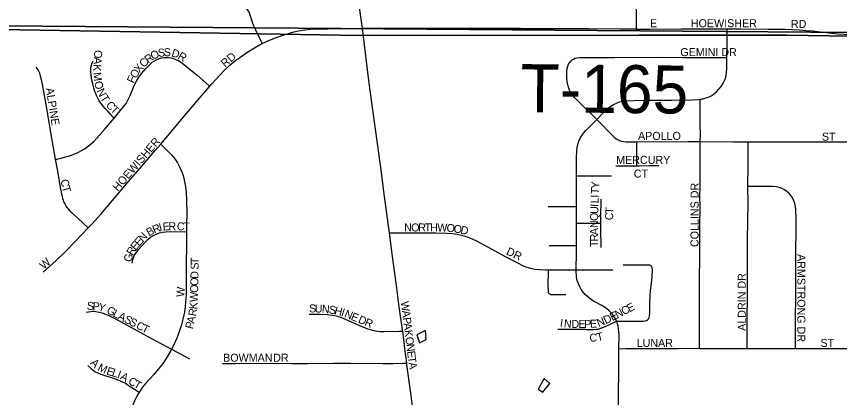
# Model space of a CAD drawing. Extents: x 0 to 1391, y -24 to 440.
# Drawn here: x 523.79 to 543.27, y 306.2 to 315.22 of the extents above; entities that cross this region are included whole.
import ezdxf

# ---------------------------------------------------------------- set-up
doc = ezdxf.new("R2010")
doc.units = 0
for name, color, linetype in [('GM_X_City_Street', 7, 'Continuous'), ('GM_X_City_Street_Text', 7, 'Continuous'), ('GM_X_Corporation', 7, 'Continuous'), ('GM_X_County_Road', 7, 'Continuous'), ('GM_X_Minor_Lake', 7, 'Continuous'), ('GM_X_Section', 7, 'Continuous'), ('GM_X_Township', 7, 'Continuous'), ('GM_X_Township_Road', 7, 'Continuous'), ('GM_X_Township_Road_Text', 7, 'Continuous')]:
    doc.layers.add(name, color=color, linetype=linetype)

msp = doc.modelspace()

# ---------------------------------------------------------------- linework, layer by layer
at = {"layer": 'GM_X_City_Street'}
for points in [[(529.045, 315.613), (529.052, 315.609), (529.108, 315.56), (529.165, 315.505), (529.199, 315.464), (529.232, 315.42), (529.255, 315.388), (529.279, 315.35), (529.299, 315.313), (529.312, 315.277), (529.327, 315.232), (529.362, 315.114), (529.38, 315.062), (529.398, 315.022), (529.424, 314.959), (529.448, 314.908), (529.596, 314.613), (529.611, 314.582)], [(529.611, 314.582), (529.779, 314.661), (529.965, 314.733), (530.154, 314.796), (530.358, 314.854), (530.468, 314.88), (530.615, 314.906), (530.752, 314.923), (530.926, 314.932), (531.163, 314.932), (531.986, 314.935)], [(532.618, 310.102), (532.588, 310.318), (532.505, 310.958), (532.413, 311.648), (532.256, 312.781), (532.14, 313.643), (531.986, 314.935)], [(538.458, 314.922), (538.771, 314.921), (539.529, 314.926), (539.927, 314.929), (540.474, 314.929), (540.607, 314.929)], [(540.605, 314.252), (540.608, 314.566), (540.608, 314.814), (540.607, 314.929)], [(540.607, 314.929), (540.934, 314.929), (541.58, 314.924), (541.99, 314.917), (542.322, 314.902), (542.47, 314.89), (542.63, 314.877), (542.808, 314.859), (543.23, 314.813), (543.377, 314.799), (543.51, 314.787)], [(528.37, 313.568), (528.42, 313.627), (528.611, 313.84), (528.715, 313.948), (528.844, 314.066), (528.989, 314.186), (529.078, 314.253), (529.243, 314.366), (529.423, 314.478), (529.575, 314.565), (529.611, 314.582)], [(526.104, 312.814), (526.075, 312.847), (525.964, 312.969), (525.903, 313.036), (525.846, 313.1), (525.822, 313.131), (525.793, 313.169), (525.771, 313.203), (525.747, 313.243), (525.716, 313.301), (525.691, 313.354), (525.671, 313.399), (525.653, 313.446), (525.634, 313.5), (525.619, 313.553), (525.601, 313.628), (525.582, 313.711), (525.561, 313.833), (525.553, 313.92), (525.552, 313.944), (525.554, 313.982), (525.557, 314.008), (525.563, 314.043), (525.57, 314.071), (525.58, 314.103), (525.594, 314.137), (525.61, 314.172)], [(526.104, 312.814), (526.321, 313.071), (526.387, 313.161), (526.425, 313.225), (526.479, 313.337), (526.541, 313.488), (526.575, 313.569), (526.608, 313.64), (526.635, 313.69), (526.693, 313.785), (526.759, 313.875), (526.856, 313.989), (526.943, 314.078), (527.008, 314.136), (527.057, 314.172), (527.116, 314.202), (527.176, 314.227), (527.227, 314.24), (527.278, 314.249), (527.331, 314.253), (527.393, 314.252), (527.454, 314.243), (527.514, 314.227), (527.583, 314.198), (527.627, 314.177), (527.662, 314.156), (527.702, 314.13), (527.742, 314.1), (527.829, 314.03), (528.067, 313.83), (528.346, 313.589), (528.37, 313.568)], [(537.525, 312.783), (537.187, 313.116), (537.01, 313.292), (536.952, 313.358), (536.922, 313.4), (536.89, 313.456), (536.861, 313.527), (536.839, 313.6), (536.826, 313.675), (536.819, 313.789), (536.819, 313.915), (536.826, 313.991), (536.837, 314.042), (536.856, 314.091), (536.877, 314.125), (536.911, 314.166), (536.941, 314.192), (536.975, 314.214), (537.011, 314.23), (537.05, 314.24), (537.114, 314.248), (537.227, 314.251), (537.624, 314.248), (537.947, 314.249), (538.966, 314.254), (539.55, 314.249), (540.356, 314.249), (540.48, 314.25), (540.605, 314.252)], [(539.972, 313.262), (540.012, 313.267), (540.082, 313.284), (540.139, 313.299), (540.182, 313.315), (540.229, 313.34), (540.271, 313.368), (540.319, 313.402), (540.361, 313.439), (540.414, 313.498), (540.468, 313.563), (540.508, 313.624), (540.542, 313.688), (540.568, 313.755), (540.587, 313.825), (540.598, 313.897), (540.603, 313.982), (540.605, 314.193), (540.605, 314.252)], [(524.719, 311.84), (524.671, 312.112), (524.618, 312.43), (524.529, 312.957), (524.443, 313.447), (524.395, 313.69), (524.366, 313.811), (524.357, 313.843), (524.345, 313.879), (524.337, 313.896), (524.322, 313.928), (524.306, 313.955), (524.285, 313.989), (524.262, 314.021)], [(527.207, 312.202), (527.492, 312.54), (527.733, 312.825), (528.041, 313.182), (528.37, 313.568)], [(537.525, 312.783), (537.687, 312.948), (537.798, 313.05), (537.824, 313.072), (537.858, 313.096), (537.922, 313.137), (537.991, 313.171), (538.063, 313.197), (538.137, 313.215), (538.213, 313.225), (538.4, 313.233), (538.699, 313.239), (539.295, 313.243), (539.779, 313.249), (539.927, 313.257), (539.972, 313.262)], [(539.975, 312.261), (539.977, 312.428), (539.975, 312.652), (539.973, 313.112), (539.972, 313.262)], [(524.719, 311.84), (524.747, 311.846), (524.88, 311.878), (524.934, 311.889), (524.988, 311.903), (525.047, 311.922), (525.094, 311.939), (525.243, 312.001), (525.332, 312.046), (525.417, 312.098), (525.47, 312.133), (525.527, 312.179), (525.622, 312.261), (525.7, 312.341), (525.879, 312.548), (526.104, 312.814)], [(537.049, 311.45), (537.049, 311.632), (537.048, 311.894), (537.054, 312.032), (537.065, 312.12), (537.081, 312.194), (537.104, 312.267), (537.134, 312.337), (537.172, 312.404), (537.217, 312.465), (537.267, 312.522), (537.525, 312.783)], [(537.525, 312.783), (537.596, 312.711), (537.847, 312.453), (537.937, 312.365), (537.988, 312.326), (538.044, 312.293), (538.105, 312.27), (538.156, 312.258), (538.219, 312.252), (538.471, 312.253)], [(525.495, 310.218), (525.587, 310.314), (525.794, 310.545), (526.109, 310.912), (526.435, 311.304), (526.719, 311.633), (527.067, 312.038), (527.207, 312.202)], [(527.207, 312.202), (527.227, 312.182), (527.387, 312.024), (527.463, 311.944), (527.54, 311.848), (527.602, 311.757), (527.655, 311.66), (527.7, 311.56), (527.736, 311.456), (527.773, 311.313), (527.794, 311.192), (527.808, 311.058), (527.815, 310.872), (527.824, 310.55), (527.821, 310.289), (527.819, 310.12)], [(538.471, 312.253), (539.684, 312.261), (539.975, 312.261)], [(538.477, 311.688), (538.476, 311.736), (538.474, 311.846), (538.471, 312.042), (538.471, 312.153), (538.471, 312.253)], [(539.959, 307.364), (539.959, 307.46), (539.957, 307.843), (539.959, 308.054), (539.958, 308.179), (539.958, 308.452), (539.958, 309.048), (539.964, 309.458), (539.966, 309.645), (539.963, 309.968), (539.962, 310.29), (539.968, 310.688), (539.967, 310.999), (539.969, 311.16), (539.975, 311.608), (539.972, 311.981), (539.975, 312.261)], [(539.975, 312.261), (540.751, 312.256), (541.105, 312.254)], [(541.1, 311.196), (541.107, 311.713), (541.106, 312.098), (541.105, 312.254)], [(541.105, 312.254), (541.372, 312.253), (542.688, 312.25), (542.949, 312.251), (543.357, 312.251), (543.495, 312.251)], [(525.495, 310.218), (525.486, 310.226), (525.244, 310.445), (525.091, 310.591), (525.047, 310.639), (525.016, 310.674), (524.994, 310.703), (524.972, 310.734), (524.954, 310.765), (524.936, 310.799), (524.919, 310.834), (524.907, 310.867), (524.895, 310.906), (524.882, 310.951), (524.843, 311.133), (524.762, 311.598), (524.719, 311.84)], [(537.975, 311.687), (538.477, 311.688)], [(538.477, 311.688), (538.54, 311.688), (538.774, 311.693), (538.992, 311.696)], [(537.047, 310.721), (537.049, 311.26), (537.049, 311.45)], [(537.049, 311.45), (537.191, 311.449), (537.381, 311.449), (537.756, 311.448), (537.872, 311.45)], [(541.086, 307.361), (541.086, 307.552), (541.085, 308.086), (541.089, 308.583), (541.091, 308.931), (541.094, 309.278), (541.093, 309.639), (541.095, 309.962), (541.097, 310.334), (541.104, 310.831), (541.1, 311.154), (541.1, 311.196)], [(542.229, 307.36), (542.229, 307.488), (542.23, 308.097), (542.232, 308.569), (542.238, 309.687), (542.24, 310.134), (542.24, 310.457), (542.239, 310.643), (542.231, 310.717), (542.215, 310.79), (542.191, 310.86), (542.158, 310.927), (542.123, 310.979), (542.082, 311.025), (542.026, 311.074), (541.965, 311.117), (541.91, 311.145), (541.84, 311.171), (541.767, 311.187), (541.693, 311.195), (541.457, 311.197), (541.283, 311.199), (541.246, 311.199), (541.1, 311.196)], [(537.625, 310.325), (537.625, 310.464), (537.628, 310.9)], [(536.379, 310.724), (536.578, 310.723), (536.908, 310.722), (537.047, 310.721)], [(537.045, 310.33), (537.046, 310.428), (537.047, 310.721)], [(537.042, 309.799), (537.045, 310.33)], [(537.045, 310.33), (537.175, 310.328), (537.321, 310.326), (537.446, 310.326), (537.571, 310.326), (537.625, 310.325)], [(537.626, 309.753), (537.625, 310.187), (537.625, 310.325)], [(524.43, 309.166), (524.736, 309.446), (524.941, 309.643), (525.2, 309.911), (525.495, 310.218)], [(526.532, 309.384), (526.548, 309.47), (526.563, 309.517), (526.583, 309.562), (526.616, 309.615), (526.686, 309.702), (526.832, 309.87), (526.902, 309.94), (526.97, 309.994), (527.022, 310.027), (527.1, 310.066), (527.181, 310.097), (527.253, 310.115), (527.326, 310.126), (527.438, 310.13), (527.796, 310.121), (527.819, 310.12)], [(527.819, 310.12), (527.816, 309.855), (527.813, 309.308), (527.814, 308.873), (527.808, 308.638), (527.785, 308.354), (527.767, 308.22), (527.74, 308.087), (527.689, 307.896), (527.637, 307.731), (527.589, 307.605), (527.518, 307.447), (527.465, 307.343)], [(532.618, 310.102), (532.813, 310.1), (533.379, 310.096), (533.715, 310.096), (533.975, 310.095), (534.11, 310.086), (534.22, 310.071), (534.328, 310.047), (534.434, 310.016), (534.537, 309.977), (534.66, 309.92), (534.956, 309.763), (535.359, 309.541), (535.667, 309.378), (535.78, 309.322), (535.874, 309.285), (535.959, 309.26), (536.058, 309.24), (536.159, 309.229), (536.309, 309.223), (536.38, 309.223)], [(532.933, 307.773), (532.929, 307.805), (532.852, 308.347), (532.785, 308.851), (532.695, 309.542), (532.618, 310.102)], [(536.402, 309.798), (536.577, 309.798), (536.761, 309.799), (536.934, 309.799), (537.042, 309.799)], [(537.04, 309.224), (537.042, 309.645), (537.042, 309.799)], [(537.992, 308.011), (538.257, 308.011), (538.41, 308.009), (538.62, 308.01), (538.666, 308.016), (538.698, 308.026), (538.727, 308.042), (538.749, 308.064), (538.763, 308.092), (538.772, 308.125), (538.777, 308.196), (538.784, 308.444), (538.786, 308.607), (538.796, 308.732), (538.819, 308.905), (538.836, 309.064), (538.843, 309.235), (538.838, 309.269), (538.827, 309.299), (538.815, 309.314), (538.8, 309.325), (538.781, 309.332), (538.736, 309.335), (538.4, 309.334), (538.151, 309.337)], [(536.795, 308.632), (536.467, 308.629), (536.436, 308.635), (536.417, 308.645), (536.394, 308.665), (536.384, 308.68), (536.38, 308.7), (536.379, 308.909), (536.38, 309.127), (536.38, 309.223)], [(536.38, 309.223), (536.63, 309.223), (536.88, 309.224), (537.04, 309.224)], [(537.992, 308.011), (537.975, 308.045), (537.95, 308.09), (537.922, 308.133), (537.886, 308.179), (537.85, 308.221), (537.812, 308.26), (537.762, 308.301), (537.708, 308.34), (537.644, 308.38), (537.462, 308.478), (537.378, 308.533), (537.318, 308.58), (537.262, 308.632), (537.211, 308.689), (537.16, 308.762), (537.118, 308.84), (537.092, 308.894), (537.074, 308.935), (537.061, 308.973), (537.052, 309.011), (537.047, 309.06), (537.04, 309.197), (537.04, 309.224)], [(537.04, 309.224), (537.459, 309.22), (537.802, 309.22), (537.902, 309.22)], [(525.444, 308.225), (525.502, 308.233), (525.556, 308.24), (525.595, 308.242), (525.637, 308.242), (525.676, 308.237), (525.715, 308.232), (525.752, 308.225), (525.821, 308.206), (525.88, 308.184), (525.966, 308.148), (526.136, 308.062), (526.345, 307.951), (526.868, 307.665), (527.108, 307.535), (527.465, 307.343)], [(530.722, 308.176), (530.965, 308.178), (531.151, 308.166), (531.274, 308.151), (531.359, 308.133), (531.416, 308.117), (531.466, 308.101), (531.57, 308.059), (531.966, 307.88), (532.027, 307.855), (532.082, 307.836), (532.189, 307.804), (532.245, 307.789), (532.298, 307.78), (532.396, 307.767), (532.496, 307.763), (532.854, 307.771), (532.933, 307.773)], [(536.606, 307.823), (536.803, 307.821), (537.125, 307.819), (537.262, 307.816), (537.29, 307.815), (537.328, 307.814), (537.354, 307.814), (537.363, 307.814), (537.393, 307.814), (537.449, 307.814), (537.509, 307.816), (537.558, 307.823), (537.618, 307.84), (537.767, 307.901), (537.858, 307.946), (537.992, 308.011)], [(538.051, 307.357), (538.053, 307.689), (538.05, 307.768), (538.043, 307.831), (538.032, 307.891), (538.018, 307.941), (537.998, 307.997), (537.992, 308.011)], [(533.029, 307.017), (532.986, 307.361), (532.933, 307.773)], [(527.465, 307.343), (527.451, 307.315), (527.364, 307.166), (527.283, 307.042), (527.194, 306.924), (527.043, 306.744), (526.859, 306.542), (526.78, 306.444), (526.709, 306.34), (526.701, 306.326)], [(527.465, 307.343), (527.475, 307.337), (527.8, 307.167), (527.889, 307.121)], [(538.092, 304.699), (538.09, 304.733), (538.068, 305.03), (538.054, 305.354), (538.049, 305.664), (538.043, 306.124), (538.048, 306.982), (538.051, 307.357)], [(538.051, 307.357), (538.208, 307.36), (538.458, 307.364), (539.055, 307.361), (539.452, 307.362), (539.725, 307.366), (539.959, 307.364)], [(539.959, 307.364), (540.397, 307.36), (541.086, 307.361)], [(541.086, 307.361), (541.366, 307.362), (542.061, 307.359), (542.229, 307.36)], [(542.229, 307.36), (542.534, 307.36), (543.242, 307.362), (543.329, 307.361), (543.483, 307.36)], [(525.482, 306.956), (525.568, 306.88), (525.627, 306.835), (525.664, 306.812), (525.703, 306.792), (525.752, 306.771), (525.794, 306.753), (526.127, 306.646), (526.232, 306.607), (526.322, 306.564), (526.372, 306.538), (526.441, 306.496), (526.671, 306.346), (526.701, 306.326)], [(528.667, 307.005), (528.976, 307.007), (529.348, 307.012), (529.622, 307.009), (529.883, 307.011), (530.305, 307.01), (530.678, 307.009), (531.287, 307.013), (531.71, 307.013), (532.455, 307.01), (532.716, 307.009), (532.929, 307.014), (533.029, 307.017)], [(533.208, 305.671), (533.179, 305.883), (533.119, 306.363), (533.033, 306.979), (533.029, 307.017)], [(526.701, 306.326), (526.645, 306.232), (526.589, 306.12), (526.541, 306.004), (526.511, 305.915)]]:
    msp.add_lwpolyline(points, dxfattribs=at)
at = {"layer": 'GM_X_Corporation'}
msp.add_lwpolyline([(543.512, 319.472), (541.992, 319.486), (542.007, 316.193), (538.456, 316.162), (538.458, 314.922), (535.727, 314.933), (531.986, 314.935), (531.717, 316.828), (528.397, 316.553), (528.413, 317.001), (529.778, 317.193), (530.212, 317.944), (531.533, 318.118), (531.399, 319.019), (532.093, 319.148), (531.917, 320.165), (531.256, 320.053), (531.2, 320.498), (530.847, 320.443), (530.739, 321.001), (530.415, 321.61), (529.673, 321.397), (527.382, 319.542), (523.111, 315.958)], dxfattribs=at)
at = {"layer": 'GM_X_County_Road'}
msp.add_lwpolyline([(531.986, 314.935), (531.89, 315.606), (531.819, 316.096), (531.756, 316.551), (531.717, 316.828)], dxfattribs=at)
at = {"layer": 'GM_X_Minor_Lake'}
for p, q in [((533.49, 307.572), (533.471, 307.786)), ((533.271, 307.684), (533.328, 307.497)), ((533.328, 307.497), (533.49, 307.572)), ((536.253, 306.328), (536.413, 306.532)), ((536.413, 306.532), (536.279, 306.65)), ((536.142, 306.397), (536.253, 306.328))]:
    msp.add_line(p, q, dxfattribs=at)
for points in [[(533.471, 307.786), (533.271, 307.684)], [(536.279, 306.65), (536.142, 306.397)]]:
    msp.add_lwpolyline(points, dxfattribs=at)
at = {"layer": 'GM_X_Section'}
for points in [[(543.597, 335.27), (543.606, 334.944), (543.593, 314.84), (523.385, 314.999), (523.728, 335.34)], [(543.593, 314.84), (543.458, 295.101), (523.431, 295.166), (523.385, 314.999)]]:
    msp.add_lwpolyline(points, close=True, dxfattribs=at)
at = {"layer": 'GM_X_Township'}
for points in [[(492, 418), (492, 315.227), (495.169, 315.241), (498.514, 315.204), (501.039, 315.287), (503.177, 315.368), (505.882, 315.221), (509.415, 315.098), (514.601, 314.991), (521.022, 314.955), (531.927, 314.772), (538.532, 314.775), (540.688, 314.776), (542.014, 314.776), (543.525, 314.752), (551.45, 314.755), (558.142, 314.749), (563.346, 314.735), (563.436, 326.438), (563.505, 334.791), (563.576, 343.168), (563.677, 355.031), (563.749, 363.357), (563.752, 363.742)], [(569.034, 282), (570.417, 295.228), (570.942, 300.256), (569.679, 300.135), (568.293, 300.179), (566.907, 300.044), (565.297, 300.626), (564.499, 300.973), (563.262, 301.241), (563.248, 301.521), (563.269, 304.402), (563.335, 313.31), (563.346, 314.735), (558.142, 314.749), (551.45, 314.755), (543.525, 314.752), (542.014, 314.776), (540.688, 314.776), (538.532, 314.775), (531.927, 314.772), (521.022, 314.955)]]:
    msp.add_lwpolyline(points, dxfattribs=at)
at = {"layer": 'GM_X_Township_Road'}
for points in [[(531.986, 314.935), (532.58, 314.929), (532.891, 314.932), (533.177, 314.931), (533.488, 314.931), (533.836, 314.929), (534.084, 314.927), (534.445, 314.929), (534.843, 314.928), (535.341, 314.93), (535.727, 314.933)], [(535.727, 314.933), (536.176, 314.936), (536.821, 314.933), (537.33, 314.933), (538.074, 314.927), (538.458, 314.922)]]:
    msp.add_lwpolyline(points, dxfattribs=at)

# ---------------------------------------------------------------- texts
at = {"layer": 'GM_X_City_Street_Text'}
for s, height, rotation, p in [('E', 0.189, 0, (538.785, 314.966)), ('HOEWISHER', 0.1894, 0, (539.752, 314.966)), ('RD', 0.1894, 0, (542.119, 314.949)), ('O', 0.189, 266.939, (525.638, 314.428)), ('R', 0.189, 36.6951, (526.911, 314.101)), ('O', 0.189, 28.354, (527.025, 314.187)), ('S', 0.189, 7.9756, (527.155, 314.26)), ('S', 0.189, 1.1747, (527.281, 314.278)), ('D', 0.189, 342.2079, (527.448, 314.281)), ('R', 0.189, 329.4236, (527.596, 314.234)), ('RD', 0.1894, 40.6, (528.73, 314.008)), ('GEMINI DR', 0.1894, 0, (539.502, 314.282)), ('A', 0.189, 266.4564, (525.629, 314.262)), ('C', 0.189, 45.0343, (526.81, 314)), ('K', 0.189, 265.2962, (525.619, 314.097)), ('O', 0.189, 57.1952, (526.621, 313.739)), ('X', 0.189, 50.7598, (526.708, 313.874)), ('M', 0.189, 276.8989, (525.606, 313.889)), ('F', 0.189, 64.9748, (526.568, 313.624)), ('O', 0.189, 282.8709, (525.633, 313.669)), ('ALPINE', 0.1894, 279.2699, (524.487, 313.518)), ('N', 0.189, 296.2526, (525.687, 313.461)), ('T', 0.189, 301.6039, (525.77, 313.295)), ('C', 0.189, 313.6611, (525.897, 313.108)), ('T', 0.189, 314.9759, (526.004, 312.996)), ('APOLLO', 0.1894, 0, (538.502, 312.299)), ('ST', 0.1894, 0, (542.852, 312.282)), ('HOEWISHER', 0.1894, 49.3328, (526.192, 311.07)), ('MERCURY', 0.1894, 0, (537.985, 311.732)), ('CT', 0.1894, 0, (538.402, 311.407)), ('C', 0.189, 280.0572, (524.838, 311.351)), ('T', 0.189, 285.4723, (524.868, 311.184)), ('Y', 0.189, 87.836, (537.58, 311.144)), ('COLLINS DR', 0.1894, 90, (539.933, 309.763)), ('T', 0.189, 87.8415, (537.575, 311.011)), ('L', 0.189, 87.8448, (537.567, 310.795)), ('I', 0.189, 87.8579, (537.572, 310.928)), ('U', 0.189, 87.9671, (537.558, 310.545)), ('I', 0.189, 87.8142, (537.564, 310.711)), ('T', 0.189, 86.255, (537.915, 310.543)), ('Q', 0.189, 88.929, (537.555, 310.379)), ('C', 0.189, 87.6434, (537.909, 310.395)), ('B', 0.189, 28.7597, (526.929, 310.011)), ('R', 0.189, 21.0619, (527.054, 310.08)), ('I', 0.189, 13.8665, (527.188, 310.133)), ('E', 0.189, 4.868, (527.261, 310.151)), ('R', 0.189, 359.5385, (527.39, 310.162)), ('C', 0.189, 358.7708, (527.589, 310.16)), ('T', 0.189, 358.7707, (527.739, 310.157)), ('N', 0.189, 359.9563, (532.969, 310.132)), ('O', 0.189, 359.9563, (533.135, 310.132)), ('R', 0.189, 359.9703, (533.302, 310.132)), ('T', 0.189, 359.9454, (533.452, 310.132)), ('H', 0.189, 359.9703, (533.585, 310.132)), ('W', 0.189, 359.1763, (533.751, 310.132)), ('O', 0.189, 353.6936, (533.963, 310.129)), ('O', 0.189, 351.7741, (534.127, 310.111)), ('D', 0.189, 346.4303, (534.288, 310.088)), ('N', 0.189, 89.9563, (537.555, 310.213)), ('N', 0.189, 46.6383, (526.788, 309.869)), ('R', 0.189, 89.9703, (537.555, 309.897)), ('A', 0.189, 89.9703, (537.555, 310.047)), ('E', 0.189, 50.2819, (526.617, 309.668)), ('E', 0.189, 49.0608, (526.702, 309.769)), ('T', 0.189, 89.9727, (537.555, 309.763)), ('R', 0.189, 57.974, (526.541, 309.546)), ('DR', 0.1894, 334.8032, (535.367, 309.596)), ('W', 0.189, 41.9775, (524.445, 309.223)), ('G', 0.189, 79.0245, (526.516, 309.399)), ('T', 0.189, 88.9781, (528.106, 309.361)), ('ARMSTRONG DR', 0.18939, 270, (542.271, 309.597)), ('S', 0.189, 88.9345, (528.103, 309.228)), ('D', 0.189, 88.9569, (528.099, 309.011)), ('ALDRIN DR', 0.1894, 90, (541.051, 307.78)), ('O', 0.189, 88.9343, (528.096, 308.844)), ('W', 0.189, 86.3995, (527.766, 308.577)), ('W', 0.189, 87.4515, (528.082, 308.456)), ('O', 0.189, 88.6642, (528.092, 308.677)), ('W', 0.189, 277.2147, (532.887, 308.468)), ('S', 0.189, 355.7898, (525.455, 308.282)), ('P', 0.189, 356.5313, (525.591, 308.272)), ('Y', 0.189, 344.3098, (525.713, 308.266)), ('G', 0.189, 333.2688, (525.911, 308.205)), ('L', 0.189, 332.6895, (526.059, 308.13)), ('R', 0.189, 80.2153, (528.042, 308.116)), ('K', 0.189, 85.6466, (528.069, 308.283)), ('S', 0.189, 359.6448, (530.718, 308.216)), ('U', 0.189, 358.4477, (530.851, 308.215)), ('N', 0.189, 354.4177, (531.014, 308.211)), ('S', 0.189, 351.4179, (531.177, 308.195)), ('H', 0.189, 345.6403, (531.304, 308.176)), ('I', 0.189, 341.5927, (531.462, 308.136)), ('N', 0.189, 27.23, (538.013, 308.069)), ('C', 0.189, 27.2167, (538.161, 308.146)), ('E', 0.189, 27.2061, (538.294, 308.214)), ('A', 0.189, 332.7097, (526.178, 308.069)), ('S', 0.189, 332.6895, (526.326, 307.993)), ('A', 0.189, 76.4697, (528, 307.941)), ('N', 0.189, 338.1418, (531.538, 308.11)), ('E', 0.189, 337.2856, (531.692, 308.048)), ('D', 0.189, 337.4412, (531.862, 307.978)), ('A', 0.189, 277.2091, (532.915, 308.253)), ('P', 0.189, 277.2029, (532.936, 308.088)), ('N', 0.189, 21.0649, (537.567, 307.87)), ('D', 0.189, 24.9335, (537.735, 307.935)), ('E', 0.189, 26.848, (537.893, 308.009)), ('S', 0.189, 332.7064, (526.444, 307.932)), ('C', 0.189, 332.7074, (526.607, 307.848)), ('T', 0.189, 332.6895, (526.741, 307.779)), ('P', 0.189, 75.9836, (527.967, 307.81)), ('R', 0.189, 337.4231, (532.016, 307.914)), ('A', 0.189, 277.2091, (532.952, 307.955)), ('I', 0.189, 350.6886, (536.644, 307.881)), ('N', 0.189, 354.417, (536.74, 307.866)), ('D', 0.189, 0.2179, (536.926, 307.849)), ('E', 0.189, 0.2836, (537.093, 307.85)), ('P', 0.189, 0.2732, (537.227, 307.85)), ('E', 0.189, 2.2403, (537.367, 307.851)), ('K', 0.189, 277.2091, (532.973, 307.79)), ('C', 0.189, 1.2628, (537.353, 307.523)), ('T', 0.189, 13.1739, (537.546, 307.532)), ('O', 0.189, 277.2091, (532.994, 307.625)), ('LUNAR', 0.1894, 0, (538.469, 307.399)), ('ST', 0.1894, 0, (542.819, 307.399)), ('N', 0.189, 277.2091, (533.015, 307.459)), ('BOWMAN', 0.1894, 0, (528.685, 307.049)), ('DR', 0.1894, 0, (529.869, 307.049)), ('E', 0.189, 277.2357, (533.036, 307.294)), ('T', 0.189, 277.562, (533.053, 307.16)), ('A', 0.189, 315.4327, (525.528, 307.005)), ('M', 0.189, 334.0601, (525.701, 306.849)), ('E', 0.189, 343.1034, (525.911, 306.75)), ('A', 0.189, 279.063, (533.071, 307.023)), ('L', 0.189, 342.5156, (526.038, 306.711)), ('I', 0.189, 339.27, (526.163, 306.672)), ('A', 0.189, 331.3721, (526.234, 306.646)), ('C', 0.189, 328.5405, (526.421, 306.541)), ('T', 0.189, 329.7243, (526.553, 306.461))]:
    msp.add_text(s, height=height, rotation=rotation, dxfattribs=at).set_placement(p)
at = {"layer": 'GM_X_Township_Road_Text'}
msp.add_text('T-165', height=1.1364, rotation=359.4503, dxfattribs=at).set_placement((535.716, 312.958))

doc.saveas('drawing.dxf')
